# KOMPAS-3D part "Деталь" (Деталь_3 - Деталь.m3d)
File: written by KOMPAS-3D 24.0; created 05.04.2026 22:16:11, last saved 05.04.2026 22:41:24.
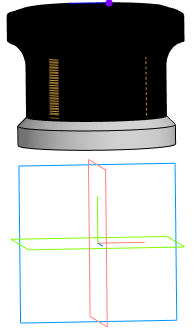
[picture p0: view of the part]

Document properties: Автор: tyuri; Полное имя файла: D:\Аутсорс\Клапан балансировочный автоматический DN.ru VBA0000E-T Ду15 Ру16\DN15\Исходные файлы\Деталь_3 - Деталь.m3d

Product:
- Body: Твердое тело1  | qty 1
    Масса: 0.342386
- Part/product: Деталь
    Масса: 0.342386
    additional columns: Типовые

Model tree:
1. Твердое тело1  (labels: Твердое тело1)
2. Эскиз:1  (labels: Грань.Твердое тело1)
3. Элемент выдавливания:1
     Расстояние 1 = 35.3
4. Масштабирование:1
5. Масштабирование : Ребро.Твердое тело1
6. Масштабирование : Твердое тело1  (labels: Масштабирование : Вершина.Твердое тело1; Ребро.Твердое тело1; Вершина.Твердое тело1)
     Масштаб по оси Х = 0.87301; Масштаб по оси Y = 1; Масштаб по оси Z = 0.87301; Коэффициент = 1
7. Эскиз:2  (labels: Ребро.Твердое тело1)
8. Элемент вращения:1
     Угол 1 = 360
